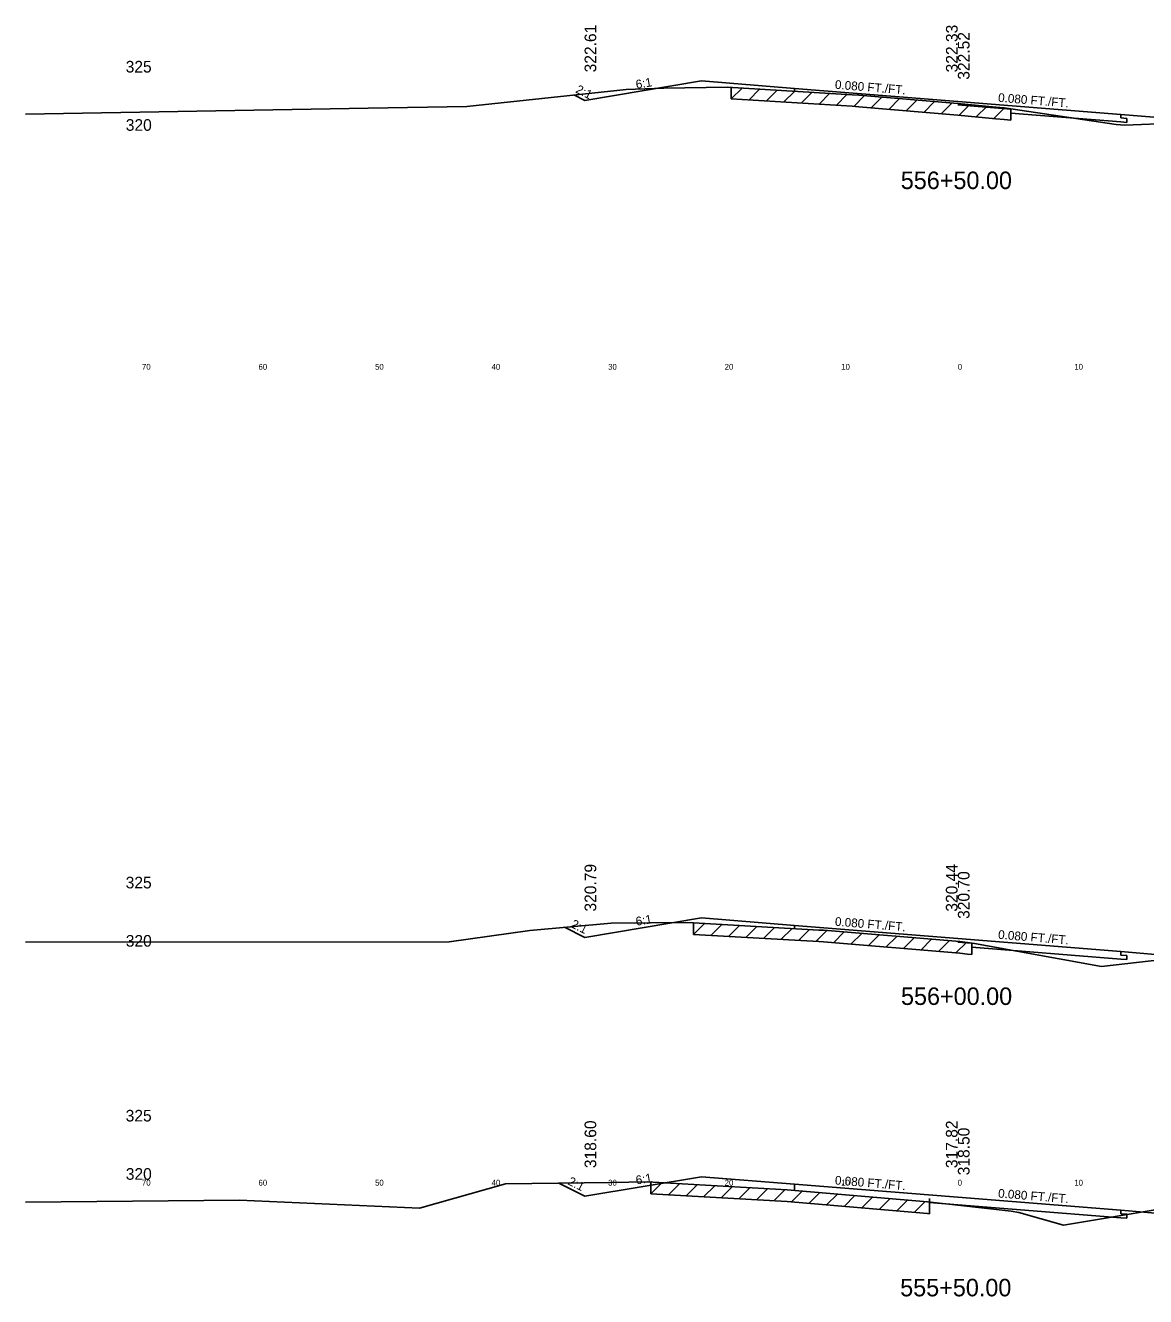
# Model space of a CAD drawing. Extents: x 1000 to 1162, y 999 to 8520.
# Drawn here: x 1000 to 1096.1, y 7590 to 7699 of the extents above; entities that cross this region are included whole.
import ezdxf

# ---------------------------------------------------------------- set-up
doc = ezdxf.new("R2010")
doc.units = 0
for name, color, linetype in [('Level 10', 7, 'Continuous'), ('Level 11', 7, 'Continuous'), ('Level 12', 7, 'Continuous'), ('Level 3', 7, 'Continuous'), ('Level 32', 7, 'Continuous'), ('Level 33', 7, 'Continuous'), ('Level 53', 7, 'Continuous'), ('Level 56', 7, 'Continuous'), ('Level 59', 7, 'Continuous'), ('Level 6', 7, 'Continuous'), ('Level 60', 7, 'Continuous'), ('Level 61', 7, 'Continuous'), ('Level 7', 7, 'Continuous')]:
    doc.layers.add(name, color=color, linetype=linetype)

msp = doc.modelspace()

# ---------------------------------------------------------------- linework, layer by layer
at = {"layer": 'Level 11'}
for p, q in [((1066, 7693.4), (1066, 7693.64)), ((1094, 7691.1), (1094, 7691.4)), ((1094.5, 7691.06), (1094, 7691.1)), ((1094, 7690.76), (1094.5, 7690.72)), ((1094.5, 7690.72), (1094.5, 7691.06)), ((1066, 7621.55), (1066, 7621.82)), ((1094, 7619.28), (1094, 7619.58)), ((1094.5, 7619.24), (1094, 7619.28)), ((1094.5, 7618.9), (1094.5, 7619.24)), ((1094, 7618.94), (1094.5, 7618.9)), ((1066, 7599.08), (1066, 7599.62)), ((1094, 7597.08), (1094, 7597.38)), ((1094.5, 7597.04), (1094, 7597.08)), ((1094, 7596.74), (1094.5, 7596.7)), ((1094.5, 7596.7), (1094.5, 7597.04))]:
    msp.add_line(p, q, dxfattribs=at)
at = {"layer": 'Level 12'}
for p, q in [((1084.54, 7691.9), (1084.54, 7691.51)), ((1084.54, 7691.51), (1094, 7690.76)), ((1081.2, 7620.32), (1081.2, 7619.96)), ((1081.2, 7619.96), (1094, 7618.94)), ((1077.57, 7598.09), (1077.57, 7598.06)), ((1077.57, 7598.06), (1080, 7597.86)), ((1080, 7597.86), (1094, 7596.74))]:
    msp.add_line(p, q, dxfattribs=at)
at = {"layer": 'Level 53'}
for p, q in [((1080, 7692.22), (1084.54, 7691.85)), ((1080, 7620.4), (1081.2, 7620.3)), ((1077.57, 7598.4), (1077.57, 7598.09))]:
    msp.add_line(p, q, dxfattribs=at)
at = {"layer": 'Level 59'}
for p, q in [((1066, 7693.64), (1080, 7692.52)), ((1080, 7692.52), (1094, 7691.4)), ((1066, 7621.82), (1080, 7620.7)), ((1080, 7620.7), (1094, 7619.58)), ((1066, 7599.62), (1080, 7598.5)), ((1080, 7598.5), (1094, 7597.38))]:
    msp.add_line(p, q, dxfattribs=at)
at = {"layer": 'Level 6'}
for p, q in [((1058, 7694.28), (1066, 7693.64)), ((1094, 7691.4), (1102, 7690.73)), ((1058, 7622.46), (1066, 7621.82)), ((1094, 7619.58), (1102, 7618.91)), ((1058, 7600.26), (1066, 7599.62)), ((1094, 7597.38), (1102, 7596.72))]:
    msp.add_line(p, q, dxfattribs=at)
at = {"layer": 'Level 60'}
for p, q in [((1037.88, 7692.09), (1051.54, 7693.53)), ((1051.54, 7693.53), (1054.79, 7693.67)), ((1054.79, 7693.67), (1060.2, 7693.75)), ((1060.2, 7693.75), (1070.93, 7693.1)), ((1070.93, 7693.1), (1071.51, 7693.07)), ((1071.51, 7693.07), (1080, 7692.33)), ((1080, 7692.33), (1083.27, 7692.04)), ((1000, 7691.43), (1029.42, 7691.94)), ((1029.42, 7691.94), (1037.88, 7692.09)), ((1083.27, 7692.04), (1083.97, 7691.98)), ((1083.97, 7691.98), (1093.58, 7690.55)), ((1094.33, 7690.49), (1111.62, 7691.11)), ((1093.58, 7690.55), (1094.33, 7690.49)), ((1036.37, 7620.41), (1043.29, 7621.4)), ((1043.29, 7621.4), (1050.26, 7622.01)), ((1050.26, 7622.01), (1056.85, 7622.06)), ((1056.85, 7622.06), (1068.08, 7621.43)), ((1068.08, 7621.43), (1068.49, 7621.41)), ((1068.49, 7621.41), (1080.17, 7620.43)), ((1000, 7620.39), (1036.37, 7620.41)), ((1080.17, 7620.43), (1080.84, 7620.37)), ((1080.84, 7620.37), (1081.43, 7620.28)), ((1081.43, 7620.28), (1092.33, 7618.31)), ((1092.33, 7618.31), (1102.52, 7619.44)), ((1033.8, 7597.57), (1041.2, 7599.66)), ((1041.2, 7599.66), (1050.19, 7599.77)), ((1050.19, 7599.77), (1053.36, 7599.81)), ((1053.36, 7599.81), (1065.35, 7599.14)), ((1065.35, 7599.14), (1077.39, 7598.11)), ((1000, 7598.07), (1018.38, 7598.25)), ((1018.38, 7598.25), (1033.8, 7597.57)), ((1077.39, 7598.11), (1080, 7597.82)), ((1080, 7597.82), (1084.57, 7597.31)), ((1084.57, 7597.31), (1085.23, 7597.19)), ((1089.07, 7596.11), (1097.8, 7597.56)), ((1085.23, 7597.19), (1089.07, 7596.11))]:
    msp.add_line(p, q, dxfattribs=at)
at = {"layer": 'Level 61'}
for p, q in [((1060.55, 7693.73), (1060.55, 7692.73)), ((1061.5, 7693.67), (1060.55, 7692.73)), ((1063, 7693.58), (1062.06, 7692.64)), ((1064.5, 7693.49), (1063.56, 7692.55)), ((1066.01, 7693.4), (1065.06, 7692.46)), ((1067.51, 7693.31), (1066.56, 7692.37)), ((1060.55, 7692.73), (1070.93, 7692.1)), ((1069.01, 7693.22), (1068.07, 7692.27)), ((1070.51, 7693.13), (1069.57, 7692.18)), ((1072, 7693.02), (1071.07, 7692.09)), ((1073.49, 7692.9), (1072.57, 7691.98)), ((1075, 7692.76), (1074.08, 7691.84)), ((1076.5, 7692.63), (1075.58, 7691.71)), ((1078, 7692.5), (1077.08, 7691.58)), ((1079.5, 7692.37), (1078.58, 7691.45)), ((1081.01, 7692.24), (1080.08, 7691.32)), ((1070.93, 7692.1), (1071.51, 7692.07)), ((1071.51, 7692.07), (1080, 7691.33)), ((1080, 7691.33), (1083.27, 7691.04)), ((1082.51, 7692.11), (1081.59, 7691.19)), ((1084.01, 7691.98), (1083.09, 7691.06)), ((1084.54, 7690.9), (1084.54, 7691.9)), ((1083.27, 7691.04), (1083.97, 7690.98)), ((1083.97, 7690.98), (1084.54, 7690.9)), ((1057.32, 7622.03), (1057.32, 7621.03)), ((1058.27, 7621.98), (1057.32, 7621.03)), ((1059.77, 7621.89), (1058.82, 7620.95)), ((1061.27, 7621.81), (1060.32, 7620.86)), ((1062.77, 7621.73), (1061.82, 7620.78)), ((1064.27, 7621.65), (1063.33, 7620.7)), ((1065.78, 7621.56), (1064.83, 7620.61)), ((1067.28, 7621.48), (1066.33, 7620.53)), ((1068.77, 7621.39), (1067.83, 7620.45)), ((1057.32, 7621.03), (1068.08, 7620.43)), ((1068.08, 7620.43), (1068.49, 7620.41)), ((1068.49, 7620.41), (1080.17, 7619.43)), ((1070.25, 7621.26), (1069.33, 7620.34)), ((1071.76, 7621.14), (1070.83, 7620.21)), ((1073.26, 7621.01), (1072.33, 7620.09)), ((1074.76, 7620.88), (1073.84, 7619.96)), ((1076.26, 7620.76), (1075.34, 7619.83)), ((1077.76, 7620.63), (1076.84, 7619.71)), ((1079.26, 7620.5), (1078.34, 7619.58)), ((1080.77, 7620.38), (1079.84, 7619.46)), ((1081.2, 7619.32), (1081.2, 7620.32)), ((1080.17, 7619.43), (1080.84, 7619.37)), ((1080.84, 7619.37), (1081.2, 7619.32)), ((1053.67, 7599.79), (1053.67, 7598.79)), ((1054.62, 7599.74), (1053.67, 7598.79)), ((1056.13, 7599.65), (1055.18, 7598.7)), ((1057.64, 7599.57), (1056.69, 7598.62)), ((1059.15, 7599.48), (1058.19, 7598.54)), ((1053.67, 7598.79), (1065.35, 7598.14)), ((1060.65, 7599.4), (1059.7, 7598.45)), ((1062.16, 7599.31), (1061.21, 7598.37)), ((1063.67, 7599.23), (1062.72, 7598.28)), ((1065.17, 7599.15), (1064.22, 7598.2)), ((1066.66, 7599.03), (1065.73, 7598.1)), ((1068.16, 7598.9), (1067.24, 7597.98)), ((1069.67, 7598.77), (1068.74, 7597.85)), ((1071.18, 7598.64), (1070.25, 7597.72)), ((1072.68, 7598.51), (1071.76, 7597.59)), ((1065.35, 7598.14), (1077.39, 7597.11)), ((1074.19, 7598.39), (1073.26, 7597.46)), ((1075.7, 7598.26), (1074.77, 7597.34)), ((1077.2, 7598.13), (1076.28, 7597.21)), ((1077.57, 7597.09), (1077.57, 7598.09)), ((1077.39, 7597.11), (1077.57, 7597.09))]:
    msp.add_line(p, q, dxfattribs=at)
at = {"layer": 'Level 7'}
for p, q in [((1048, 7692.61), (1058, 7694.28)), ((1047.1, 7693.06), (1048, 7692.61)), ((1048, 7620.79), (1058, 7622.46)), ((1046.26, 7621.66), (1048, 7620.79)), ((1045.76, 7599.72), (1048, 7598.6)), ((1048, 7598.6), (1058, 7600.26))]:
    msp.add_line(p, q, dxfattribs=at)

# ---------------------------------------------------------------- texts
at = {"layer": 'Level 10'}
for s, p in [('322.33', (1079.99, 7695.01)), ('320.44', (1079.98, 7623)), ('317.82', (1079.98, 7601))]:
    msp.add_text(s, height=1, rotation=90, dxfattribs=at).set_placement(p)
at = {"layer": 'Level 11'}
for s, p in [(' 325', (1008.23, 7695)), (' 320', (1008.24, 7690)), (' 325', (1008.23, 7625)), (' 320', (1008.24, 7620)), (' 325', (1008.23, 7605)), (' 320', (1008.24, 7600))]:
    msp.add_text(s, height=1, dxfattribs=at).set_placement(p)
at = {"layer": 'Level 3'}
for s, p in [('556+50.00', (1075.11, 7685)), ('556+00.00', (1075.13, 7615)), ('555+50.00', (1075.06, 7590))]:
    msp.add_text(s, height=1.5, dxfattribs=at).set_placement(p)
at = {"layer": 'Level 32'}
for s, rotation, p in [('6:1', 9.4623, (1052.43, 7693.6)), ('2:1', 333.435, (1047.15, 7693.31)), ('0.080 FT./FT.', 355.4261, (1069.44, 7693.61)), ('0.080 FT./FT.', 355.4261, (1083.44, 7692.49)), ('6:1', 9.4623, (1052.43, 7621.79)), ('0.080 FT./FT.', 355.4261, (1069.44, 7621.8)), ('2:1', 333.435, (1046.74, 7621.7)), ('0.080 FT./FT.', 355.4261, (1083.44, 7620.68)), ('2:1', 333.435, (1046.48, 7599.63)), ('6:1', 9.4623, (1052.43, 7599.59)), ('0.080 FT./FT.', 355.4261, (1069.44, 7599.6)), ('0.080 FT./FT.', 355.4261, (1083.44, 7598.48))]:
    msp.add_text(s, height=0.75, rotation=rotation, dxfattribs=at).set_placement(p)
at = {"layer": 'Level 33'}
for s, p in [('322.61', (1048.98, 7695.01)), ('320.79', (1048.98, 7623.01)), ('318.60', (1048.98, 7601))]:
    msp.add_text(s, height=1, rotation=90, dxfattribs=at).set_placement(p)
at = {"layer": 'Level 56'}
for s, p in [('70', (1010, 7669.5)), ('60', (1020, 7669.5)), ('50', (1030, 7669.5)), ('40', (1040, 7669.5)), ('30', (1050, 7669.5)), ('20', (1060, 7669.5)), ('10', (1070, 7669.5)), ('0', (1080, 7669.5)), ('10', (1090, 7669.5)), ('70', (1010, 7599.5)), ('60', (1020, 7599.5)), ('50', (1030, 7599.5)), ('40', (1040, 7599.5)), ('30', (1050, 7599.5)), ('20', (1060, 7599.5)), ('10', (1070, 7599.5)), ('0', (1080, 7599.5)), ('10', (1090, 7599.5))]:
    msp.add_text(s, height=0.5, dxfattribs=at).set_placement(p)
at = {"layer": 'Level 59'}
for s, p in [(' 322.52', (1081.01, 7694.01)), (' 320.70', (1081.01, 7622.01)), (' 318.50', (1081.01, 7600.01))]:
    msp.add_text(s, height=1, rotation=90, dxfattribs=at).set_placement(p)

doc.saveas('drawing.dxf')
